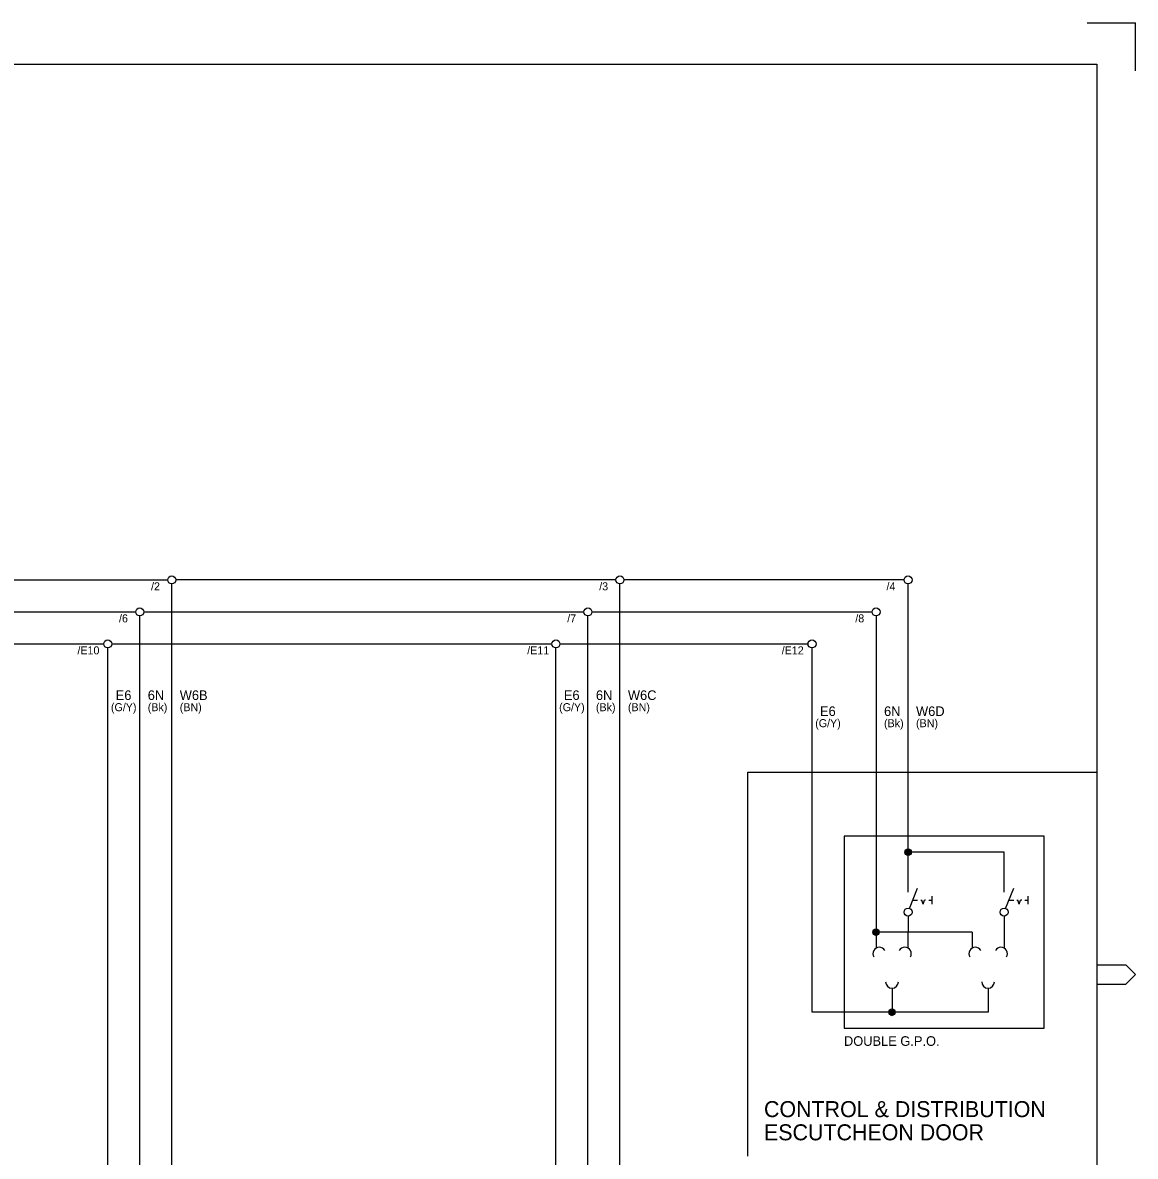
# Model space of a CAD drawing. Extents: x 0 to 841, y 0 to 594.
# Drawn here: x 493.4 to 841, y 240 to 594 of the extents above; entities that cross this region are included whole.
import ezdxf

# ---------------------------------------------------------------- set-up
doc = ezdxf.new("R2010")
doc.units = 0
for name, color, linetype in [('A1BORDER', 7, 'Continuous'), ('Level 1', 7, 'Continuous'), ('Level 10', 7, 'Continuous')]:
    doc.layers.add(name, color=color, linetype=linetype)

msp = doc.modelspace()

# ---------------------------------------------------------------- linework, layer by layer
at = {"layer": 'A1BORDER'}
for p, q in [((826, 594), (841, 594)), ((841, 579), (841, 594)), ((28, 581), (829, 581)), ((829, 581), (829, 15)), ((829, 299.76), (838, 299.76)), ((838, 299.76), (841, 296.76)), ((838, 293.76), (841, 296.76)), ((829, 293.76), (838, 293.76))]:
    msp.add_line(p, q, dxfattribs=at)
at = {"layer": 'Level 1'}
for p, q in [((421.25, 420), (538.75, 420)), ((540, 200), (540, 418.75)), ((678.75, 420), (541.25, 420)), ((680, 200), (680, 418.75)), ((768.75, 420), (681.25, 420)), ((770, 325), (770, 418.75)), ((411.25, 410), (528.75, 410)), ((530, 120), (530, 408.75)), ((531.25, 410), (668.75, 410)), ((670, 120), (670, 408.75)), ((671.25, 410), (758.75, 410)), ((760, 408.75), (760, 305)), ((391.25, 400), (518.75, 400)), ((520, 135), (520, 398.75)), ((521.25, 400), (658.75, 400)), ((660, 135), (660, 398.75)), ((661.25, 400), (738.75, 400)), ((740, 285), (740, 398.75)), ((720, 360), (829, 360)), ((720, 240), (720, 360)), ((800, 335), (770, 335)), ((800, 325), (800, 335)), ((770, 322.5), (770, 325)), ((770, 325), (770, 325)), ((770.46, 317.41), (773, 323.75)), ((800, 322.5), (800, 325)), ((800, 325), (800, 325)), ((800.46, 317.41), (803, 323.75)), ((771.5, 320), (773, 320)), ((774, 320), (774.33, 320)), ((774.75, 318.75), (774.33, 320)), ((774.75, 318.75), (775.17, 320)), ((775.5, 320), (775.17, 320)), ((776.5, 320), (777.5, 320)), ((777.5, 318.75), (777.5, 321.25)), ((801.5, 320), (803, 320)), ((804, 320), (804.33, 320)), ((804.75, 318.75), (804.33, 320)), ((804.75, 318.75), (805.17, 320)), ((805.5, 320), (805.17, 320)), ((806.5, 320), (807.5, 320)), ((807.5, 318.75), (807.5, 321.25)), ((770, 315), (769.98, 305)), ((770, 315), (770, 315)), ((800, 315), (800, 315)), ((800, 315), (800, 305)), ((760, 310), (760, 305)), ((790, 310), (760, 310)), ((790, 310), (790, 305)), ((765, 292.5), (765, 285)), ((795, 292.5), (795, 285)), ((795, 285), (740, 285))]:
    msp.add_line(p, q, dxfattribs=at)
msp.add_lwpolyline([(750, 280), (812.5, 280), (812.5, 340), (750, 340)], close=True, dxfattribs=at)
for centre in [(540, 420), (680, 420), (770, 420), (530, 410), (670, 410), (760, 410), (520, 400), (660, 400), (740, 400), (770, 316.25), (800, 316.25)]:
    msp.add_circle(centre, 1.25, dxfattribs=at)
at = {"layer": 'Level 10'}
for p, q in [((769.02, 334.89), (770.62, 335.81)), ((769.06, 335.25), (770.28, 335.96)), ((769.11, 334.59), (770.83, 335.58)), ((769.27, 334.34), (770.97, 335.32)), ((769.52, 335.87), (769.52, 335.87)), ((769.52, 334.13), (771.02, 335)), ((769.9, 334.01), (770.94, 334.61)), ((759, 309.89), (760.6, 310.81)), ((759.04, 310.25), (760.26, 310.96)), ((759.09, 309.59), (760.81, 310.58)), ((759.25, 309.34), (760.95, 310.32)), ((759.5, 310.87), (759.5, 310.87)), ((759.5, 309.13), (761, 310)), ((759.88, 309.01), (760.92, 309.61)), ((764, 284.89), (765.6, 285.81)), ((764.04, 285.25), (765.26, 285.96)), ((764.09, 284.59), (765.81, 285.58)), ((764.25, 284.34), (765.95, 285.32)), ((764.5, 285.87), (764.5, 285.87)), ((764.5, 284.13), (766, 285)), ((764.88, 284.01), (765.92, 284.61))]:
    msp.add_line(p, q, dxfattribs=at)
for centre in [(770.02, 335), (760, 310), (765, 285)]:
    msp.add_circle(centre, 1, dxfattribs=at)
for centre, start, end in [((761, 303.27), 30, 210), ((769, 303.27), 330, 150), ((791, 303.27), 30, 210), ((799.02, 303.27), 330, 150), ((765, 294.5), 180, 0), ((795, 294.5), 180, 0)]:
    msp.add_arc(centre, 2, start, end, dxfattribs=at)

# ---------------------------------------------------------------- texts
at = {"layer": 'Level 1'}
for s, height, p in [('/2', 2.5, (533.52, 416.74)), ('/3', 2.5, (673.52, 416.74)), ('/4', 2.5, (763.27, 416.74)), ('/6', 2.5, (523.52, 406.74)), ('/7', 2.5, (663.52, 406.74)), ('/8', 2.5, (753.52, 406.74)), ('/E10', 2.5, (510.53, 396.74)), ('/E11', 2.5, (651.03, 396.74)), ('/E12', 2.5, (730.53, 396.74)), ('E6', 3, (522.5, 382.5)), ('6N', 3, (532.5, 382.5)), ('W6B', 3, (542.5, 382.5)), ('E6', 3, (662.5, 382.5)), ('6N', 3, (672.5, 382.5)), ('W6C', 3, (682.5, 382.5)), ('(G/Y)', 2.5, (521, 379)), ('(Bk)', 2.5, (532.5, 379)), ('(BN)', 2.5, (542.5, 379)), ('(G/Y)', 2.5, (661, 379)), ('(Bk)', 2.5, (672.5, 379)), ('(BN)', 2.5, (682.5, 379)), ('E6', 3, (742.5, 377.5)), ('6N', 3, (762.5, 377.5)), ('W6D', 3, (772.5, 377.5)), ('(G/Y)', 2.5, (741, 374)), ('(Bk)', 2.5, (762.5, 374)), ('(BN)', 2.5, (772.5, 374)), ('DOUBLE G.P.O.', 3, (749.98, 274.5)), ('CONTROL & DISTRIBUTION', 5, (725, 252.24)), ('ESCUTCHEON DOOR', 5, (725, 245))]:
    msp.add_text(s, height=height, dxfattribs=at).set_placement(p)

doc.saveas('drawing.dxf')
